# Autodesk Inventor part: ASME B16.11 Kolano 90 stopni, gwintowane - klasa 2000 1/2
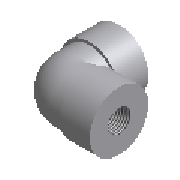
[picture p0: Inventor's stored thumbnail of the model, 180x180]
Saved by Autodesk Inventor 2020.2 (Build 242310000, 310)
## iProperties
Manager: www.cadconsulting.pl
Company: Fabian Stasiak CAD Consulting
IsCustomPart: 0
NAME: PIPING: ASME B16.11 90 Deg Elbow Threaded - Class 2000
DATA: <meta><inlinegroups number="0" deflen="0"></inlinegroups><connections number="2"></connections><angles><a>1.57079632679489</a></angles></meta>
Created: 2014-02
Part Number: ASME B16.11 Kolano 90 stopni, gwintowane - klasa 2000 1/2
Material: Stal
Description: Kolano 90º, kute, gwintowane - klasa 2000
Document SubType Name: Modeling
Standard: ASME B16.11
Designer: F.Stasiak
Standard Revision: 2005
Standards Organization: ANSI
Language: pl-PL
Size Designation: 1/2
Categories: <MemberInstance><Categories><Category DisplayName="Rury cienko- i grubościenne" InternalName="4347fa0f-2144-441d-94cd-e3e15c92b736" Mnemonic="TUBEANDPIPE"><Cate
Density: 1 g/cm^3
Appearance: Płyta
Catalog Web Link: www.expertbooks.pl
Author: F.Stasiak
Subject: Zbiór ćwiczeń. Autodesk Inventor 2020. Kurs Professional
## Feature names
1. Sweep1
2. Revolve1
3. Revolve2
4. Revolve3
5. Revolve4
6. Sweep2
## Parameters: MD = 18.32077 mm, A = 28.448 mm, L2 = 13.55598 mm, G = 3.175 mm, d0 = 18.32077 mm, d1 = 33.02 mm, d2 = 0.3124 mm, d3 = 0.3124 mm, d4 = 18.32077 mm, d5 = 33.02 mm, H = 33.02 mm, d6 = 13.55598 mm, d7 = 23.368 mm, d8 = 13.55598 mm, d9 = 23.368 mm, d10 = 0, d11 = 5.6896 mm, d12 = 5.6896 mm, d13 = 14.859 mm, d14 = 0, d101 = 90 deg, d102 = 90 deg, d105 = 25.4 mm, d106 = 0, d107 = 25.4 mm, d108 = 0, d15 = 28.448 mm, d16 = 15.6464 mm, d17 = 28.448 mm, d18 = 15.6464 mm, d19 = 29.718 mm, d20 = 29.718 mm, d21 = 5.6896 mm, d116 = 90 deg, d117 = 90 deg, d22 = 11.68403 mm, d23 = 0, d122 = 0, d123 = 0, Size_Designation = 5 mm
